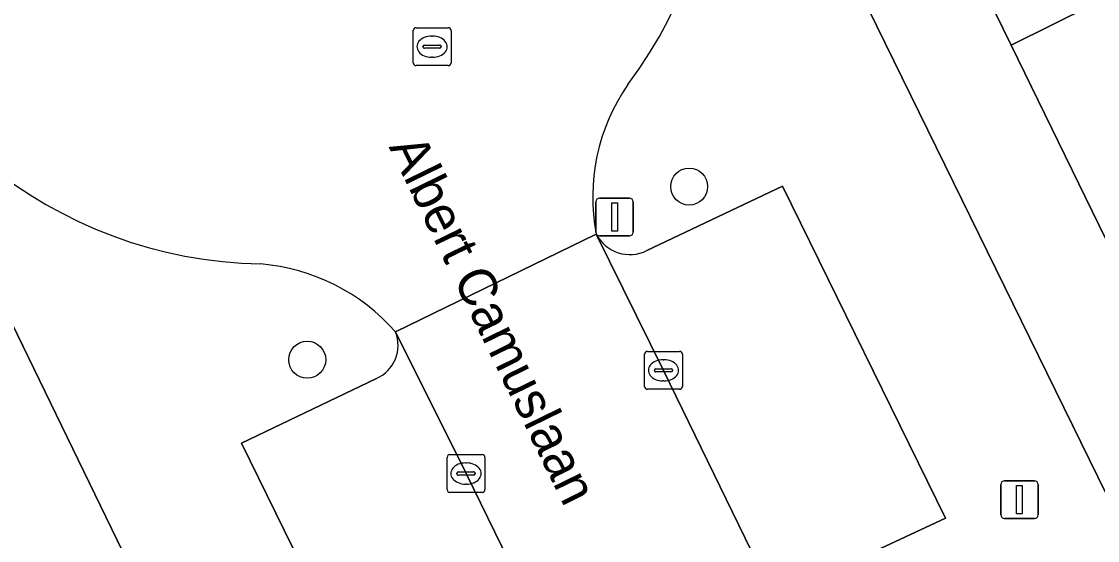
# Model space of a CAD drawing. Extents: x 160455 to 162082, y 388339 to 389736.
# Drawn here: x 160766.57 to 160795.04, y 388927.38 to 388941.1 of the extents above; entities that cross this region are included whole.
import ezdxf

# ---------------------------------------------------------------- set-up
doc = ezdxf.new("R2010")
doc.units = 0
for name, color, linetype in [('IMGEO_Boom', 7, 'Continuous'), ('IMGEO_Erf', 7, 'Continuous'), ('IMGEO_Kolk', 7, 'Continuous'), ('IMGEO_Lichtmast', 7, 'Continuous'), ('IMGEO_Openbare_ruimte_label', 7, 'Continuous'), ('IMGEO_Pand', 7, 'Continuous'), ('IMGEO_Parkeervlak_open', 7, 'Continuous'), ('IMGEO_Rijbaan_lokaal_open', 7, 'Continuous'), ('IMGEO_Rioolput', 7, 'Continuous'), ('IMGEO_Voetpad_open', 7, 'Continuous')]:
    doc.layers.add(name, color=color, linetype=linetype)

msp = doc.modelspace()

# ---------------------------------------------------------------- linework, layer by layer
at = {"layer": 'IMGEO_Boom'}
for centre in [(160784.237, 388936.735), (160774.133, 388932.16)]:
    msp.add_circle(centre, 0.489, dxfattribs=at)
at = {"layer": 'IMGEO_Erf'}
for points in [[(160800.271, 388925.116), (160797.767, 388930.233), (160795.264, 388935.349), (160792.756, 388940.475), (160790.236, 388945.627), (160791.611, 388946.301), (160791.519, 388946.489), (160790.571, 388948.432), (160789.121, 388951.402), (160786.512, 388956.747), (160784.017, 388955.533)], [(160787.173, 388945.121), (160803.386, 388912.082)], [(160781.694, 388901.467), (160765.575, 388934.628)]]:
    msp.add_lwpolyline(points, dxfattribs=at)
at = {"layer": 'IMGEO_Kolk'}
for p, q in [((160783.057, 388931.453), (160783.057, 388932.305)), ((160783.132, 388932.379), (160783.984, 388932.379)), ((160784.058, 388932.305), (160784.058, 388931.453)), ((160783.316, 388931.873), (160783.316, 388931.885)), ((160783.359, 388931.922), (160783.757, 388931.922)), ((160783.545, 388932.159), (160783.57, 388932.159)), ((160783.8, 388931.885), (160783.8, 388931.873)), ((160783.754, 388931.836), (160783.356, 388931.836)), ((160783.568, 388931.599), (160783.543, 388931.599)), ((160783.984, 388931.379), (160783.132, 388931.379)), ((160777.907, 388929.651), (160778.759, 388929.651)), ((160777.832, 388928.725), (160777.832, 388929.577)), ((160778.32, 388929.431), (160778.345, 388929.431)), ((160778.833, 388929.577), (160778.833, 388928.725)), ((160778.091, 388929.145), (160778.091, 388929.157)), ((160778.529, 388929.108), (160778.131, 388929.108)), ((160778.134, 388929.194), (160778.532, 388929.194)), ((160778.575, 388929.157), (160778.575, 388929.145)), ((160778.343, 388928.871), (160778.318, 388928.871)), ((160778.759, 388928.651), (160777.907, 388928.651))]:
    msp.add_line(p, q, dxfattribs=at)
for points in [[(160783.057, 388931.453), (160783.057, 388932.305)], [(160783.132, 388932.379), (160783.984, 388932.379)], [(160784.058, 388932.305), (160784.058, 388931.453)], [(160783.984, 388931.379), (160783.132, 388931.379)], [(160777.907, 388929.651), (160778.759, 388929.651)], [(160777.832, 388928.725), (160777.832, 388929.577)], [(160778.833, 388929.577), (160778.833, 388928.725)], [(160778.759, 388928.651), (160777.907, 388928.651)]]:
    msp.add_lwpolyline(points, dxfattribs=at)
for centre, radius, start, end in [((160783.134, 388932.303), 0.0765, 91.552, 178.448), ((160783.134, 388932.303), 0.0765, 91.552, 178.448), ((160783.982, 388932.303), 0.0765, 1.552, 88.448), ((160783.982, 388932.303), 0.0765, 1.552, 88.448), ((160783.356, 388931.882), 0.0403, 85.8775, 175.7526), ((160783.761, 388931.884), 0.0386, 1.7309, 96.639), ((160783.353, 388931.872), 0.0366, 178.938, 274.7102), ((160783.757, 388931.879), 0.043, 264.8664, 352.4533), ((160783.134, 388931.455), 0.0765, 181.552, 268.448), ((160783.134, 388931.455), 0.0765, 181.552, 268.448), ((160783.982, 388931.455), 0.0765, 271.552, 358.448), ((160783.982, 388931.455), 0.0765, 271.552, 358.448), ((160777.909, 388929.575), 0.0765, 91.552, 178.448), ((160777.909, 388929.575), 0.0765, 91.552, 178.448), ((160778.757, 388929.575), 0.0765, 1.552, 88.448), ((160778.757, 388929.575), 0.0765, 1.552, 88.448), ((160778.131, 388929.154), 0.0403, 85.8775, 175.7526), ((160778.128, 388929.144), 0.0366, 178.938, 274.7102), ((160778.532, 388929.151), 0.043, 264.8664, 352.4533), ((160778.536, 388929.156), 0.0386, 1.7309, 96.639), ((160777.909, 388928.727), 0.0765, 181.552, 268.448), ((160777.909, 388928.727), 0.0765, 181.552, 268.448), ((160778.757, 388928.727), 0.0765, 271.552, 358.448), ((160778.757, 388928.727), 0.0765, 271.552, 358.448)]:
    msp.add_arc(centre, radius, start, end, dxfattribs=at)
for centre, major_axis, ratio, start_param, end_param in [((160783.544, 388931.879), (-0.387, 0.002), 0.722429, 4.712389, 7.853982), ((160783.569, 388931.879), (-0.39, 0.002), 0.717154, 1.570796, 4.712389), ((160778.319, 388929.151), (-0.387, 0.002), 0.722429, 4.712389, 7.853982), ((160778.344, 388929.151), (-0.39, 0.002), 0.717154, 1.570796, 4.712389)]:
    msp.add_ellipse(centre, major_axis=major_axis, ratio=ratio, start_param=start_param, end_param=end_param, dxfattribs=at)
at = {"layer": 'IMGEO_Lichtmast'}
for p, q in [((160781.767, 388935.531), (160781.767, 388936.331)), ((160781.767, 388936.331), (160781.767, 388935.531)), ((160781.867, 388936.431), (160782.657, 388936.431)), ((160782.657, 388936.431), (160781.867, 388936.431)), ((160782.757, 388936.331), (160782.757, 388935.531)), ((160782.757, 388935.531), (160782.757, 388936.331)), ((160782.657, 388935.431), (160781.867, 388935.431)), ((160781.867, 388935.431), (160782.657, 388935.431)), ((160792.48, 388928.059), (160792.48, 388928.859)), ((160792.48, 388928.859), (160792.48, 388928.059)), ((160792.58, 388928.959), (160793.37, 388928.959)), ((160793.37, 388928.959), (160792.58, 388928.959)), ((160793.47, 388928.859), (160793.47, 388928.059)), ((160793.47, 388928.059), (160793.47, 388928.859)), ((160793.37, 388927.959), (160792.58, 388927.959)), ((160792.58, 388927.959), (160793.37, 388927.959))]:
    msp.add_line(p, q, dxfattribs=at)
for points in [[(160782.187, 388936.306), (160782.337, 388936.306), (160782.337, 388935.556), (160782.187, 388935.556), (160782.187, 388936.306)], [(160792.9, 388928.834), (160793.05, 388928.834), (160793.05, 388928.084), (160792.9, 388928.084), (160792.9, 388928.834)]]:
    msp.add_lwpolyline(points, dxfattribs=at)
for centre, start, end in [((160781.867, 388936.331), 90, 180), ((160781.867, 388936.331), 90, 180), ((160782.657, 388936.331), 0, 90), ((160782.657, 388936.331), 360, 90), ((160781.867, 388935.531), 180, 270), ((160781.867, 388935.531), 180, 270), ((160782.657, 388935.531), 270, 0), ((160782.657, 388935.531), 270, 0), ((160792.58, 388928.859), 90, 180), ((160792.58, 388928.859), 90, 180), ((160793.37, 388928.859), 0, 90), ((160793.37, 388928.859), 360, 90), ((160792.58, 388928.059), 180, 270), ((160792.58, 388928.059), 180, 270), ((160793.37, 388928.059), 270, 0), ((160793.37, 388928.059), 270, 0)]:
    msp.add_arc(centre, 0.1, start, end, dxfattribs=at)
at = {"layer": 'IMGEO_Pand'}
for points in [[(160799.284, 388950.064), (160791.611, 388946.301), (160790.236, 388945.627), (160792.756, 388940.475), (160800.311, 388944.226), (160800.269, 388944.463), (160799.718, 388947.594)], [(160800.311, 388944.226), (160792.756, 388940.475), (160795.264, 388935.349), (160802.818, 388939.112), (160802.771, 388939.349), (160802.335, 388941.549), (160801.67, 388944.901)]]:
    msp.add_lwpolyline(points, close=True, dxfattribs=at)
at = {"layer": 'IMGEO_Parkeervlak_open'}
for points in [[(160786.936, 388926.069), (160791.019, 388927.969), (160786.705, 388936.744), (160783.12, 388935.047)], [(160781.78, 388935.479), (160783.557, 388931.878), (160786.718, 388925.395)], [(160781.379, 388922.929), (160778.334, 388929.151), (160776.468, 388932.894)], [(160775.961, 388931.661), (160772.395, 388929.954), (160776.684, 388921.204), (160780.712, 388923.124)]]:
    msp.add_lwpolyline(points, dxfattribs=at)
for centre, radius, start, end in [((160782.668, 388935.938), 0.999, 207.3529, 296.9097), ((160775.58, 388932.538), 0.956, 293.4498, 21.846)]:
    msp.add_arc(centre, radius, start, end, dxfattribs=at)
at = {"layer": 'IMGEO_Rijbaan_lokaal_open'}
for points in [[(160786.718, 388925.395), (160783.557, 388931.878), (160781.78, 388935.479), (160776.468, 388932.894), (160778.334, 388929.151), (160781.379, 388922.929)], [(160776.468, 388932.894), (160781.78, 388935.479)]]:
    msp.add_lwpolyline(points, dxfattribs=at)
for centre, radius, start, end in [((160773.127, 388946.547), 11.859, 323.1268, 116.142), ((160773.127, 388946.547), 11.859, 116.1392, 268.92), ((160786.852, 388936.473), 5.168, 145.0829, 191.0842), ((160772.466, 388929.386), 5.322, 41.2374, 85.2859)]:
    msp.add_arc(centre, radius, start, end, dxfattribs=at)
at = {"layer": 'IMGEO_Rioolput'}
for p, q in [((160776.935, 388940.008), (160776.935, 388940.86)), ((160777.01, 388940.934), (160777.862, 388940.934)), ((160777.423, 388940.714), (160777.448, 388940.714)), ((160777.936, 388940.86), (160777.936, 388940.008)), ((160777.194, 388940.428), (160777.194, 388940.44)), ((160777.237, 388940.477), (160777.635, 388940.477)), ((160777.678, 388940.44), (160777.678, 388940.428)), ((160777.632, 388940.391), (160777.234, 388940.391)), ((160777.446, 388940.154), (160777.421, 388940.154)), ((160777.862, 388939.934), (160777.01, 388939.934))]:
    msp.add_line(p, q, dxfattribs=at)
for points in [[(160776.935, 388940.008), (160776.935, 388940.86)], [(160777.01, 388940.934), (160777.862, 388940.934)], [(160777.936, 388940.86), (160777.936, 388940.008)], [(160777.862, 388939.934), (160777.01, 388939.934)]]:
    msp.add_lwpolyline(points, dxfattribs=at)
for centre, radius, start, end in [((160777.012, 388940.858), 0.0765, 91.552, 178.448), ((160777.012, 388940.858), 0.0765, 91.552, 178.448), ((160777.86, 388940.858), 0.0765, 1.552, 88.448), ((160777.86, 388940.858), 0.0765, 1.552, 88.448), ((160777.234, 388940.437), 0.0403, 85.8775, 175.7526), ((160777.231, 388940.427), 0.0366, 178.938, 274.7102), ((160777.635, 388940.434), 0.043, 264.8664, 352.4533), ((160777.639, 388940.439), 0.0386, 1.7309, 96.639), ((160777.012, 388940.01), 0.0765, 181.552, 268.448), ((160777.012, 388940.01), 0.0765, 181.552, 268.448), ((160777.86, 388940.01), 0.0765, 271.552, 358.448), ((160777.86, 388940.01), 0.0765, 271.552, 358.448)]:
    msp.add_arc(centre, radius, start, end, dxfattribs=at)
for centre, major_axis, ratio, start_param, end_param in [((160777.422, 388940.434), (-0.387, 0.002), 0.722429, 4.712389, 7.853982), ((160777.447, 388940.434), (-0.39, 0.002), 0.717154, 1.570796, 4.712389)]:
    msp.add_ellipse(centre, major_axis=major_axis, ratio=ratio, start_param=start_param, end_param=end_param, dxfattribs=at)
at = {"layer": 'IMGEO_Voetpad_open'}
for points in [[(160813.316, 388891.537), (160812.53, 388893.161), (160810.186, 388898.103), (160806.456, 388905.785), (160803.386, 388912.082), (160787.173, 388945.121)], [(160783.12, 388935.047), (160786.705, 388936.744), (160791.019, 388927.969), (160786.936, 388926.069)], [(160765.575, 388934.628), (160781.694, 388901.467)], [(160780.712, 388923.124), (160776.684, 388921.204), (160772.395, 388929.954), (160775.961, 388931.661)]]:
    msp.add_lwpolyline(points, dxfattribs=at)
for centre, radius, start, end in [((160773.127, 388946.547), 11.859, 323.1268, 116.142), ((160773.127, 388946.547), 11.859, 116.1392, 268.92), ((160786.852, 388936.473), 5.168, 145.0829, 191.0842), ((160782.668, 388935.938), 0.999, 207.3529, 296.9097), ((160772.466, 388929.386), 5.322, 41.2374, 85.2859), ((160775.58, 388932.538), 0.956, 293.4498, 21.846)]:
    msp.add_arc(centre, radius, start, end, dxfattribs=at)

# ---------------------------------------------------------------- texts
at = {"layer": 'IMGEO_Openbare_ruimte_label'}
msp.add_text('Albert Camuslaan', height=1, rotation=296.0524, dxfattribs=at).set_placement((160776.281, 388937.785))

doc.saveas('drawing.dxf')
